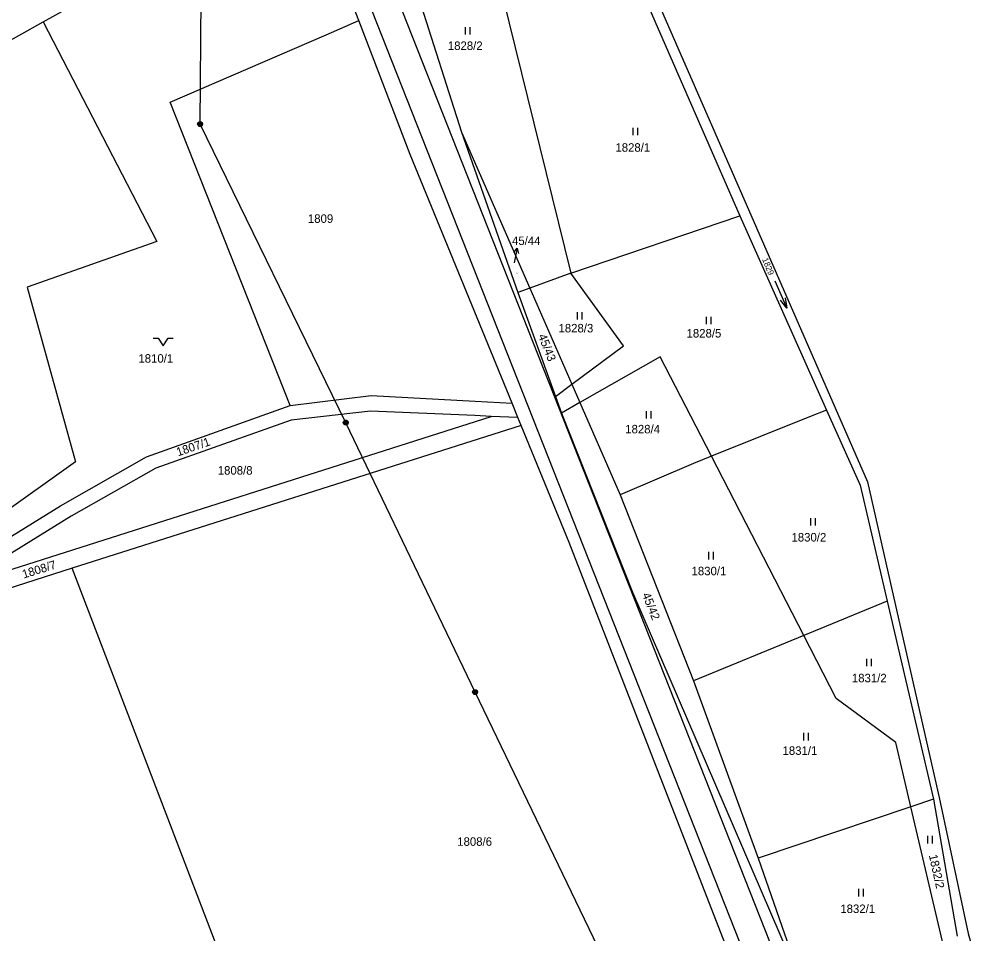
# Model space of a CAD drawing. Extents: x -609861 to -605046, y -1120287 to -1116307.
# Drawn here: x -608867.9 to -608674.5, y -1117056.1 to -1116873.3 of the extents above; entities that cross this region are included whole.
import ezdxf

# ---------------------------------------------------------------- set-up
doc = ezdxf.new("R2010")
doc.units = 0
for name, color, linetype in [('Vrstva 1', 7, 'Continuous'), ('Vrstva 2', 7, 'Continuous'), ('Vrstva 3', 7, 'Continuous'), ('Vrstva 4', 7, 'Continuous'), ('Vrstva 6', 7, 'Continuous'), ('Vrstva 7', 7, 'Continuous')]:
    doc.layers.add(name, color=color, linetype=linetype)

msp = doc.modelspace()

# ---------------------------------------------------------------- linework, layer by layer
at = {"layer": 'Vrstva 1'}
for p, q in [((-608755.13, -1116835.76), (-608704.77, -1116950.96)), ((-608756.94, -1116836.66), (-608723.86, -1116912.58)), ((-608776.76, -1116846.55), (-608757.6, -1116924.02)), ((-608799.99, -1116873.49), (-608809.1, -1116849.76)), ((-608792.64, -1116854.47), (-608779.46, -1116895.79)), ((-608863.09, -1116873.74), (-608838.32, -1116859.96)), ((-608885.48, -1116886.38), (-608863.09, -1116873.74)), ((-608863.09, -1116873.74), (-608840.34, -1116917.65)), ((-608806.56, -1116876.33), (-608799.99, -1116873.49)), ((-608789.72, -1116900.26), (-608799.99, -1116873.49)), ((-608837.71, -1116889.8), (-608806.56, -1116876.33)), ((-608813.72, -1116950.45), (-608837.71, -1116889.8)), ((-608779.46, -1116895.79), (-608768.22, -1116927.91)), ((-608779.46, -1116895.79), (-608765.81, -1116927.03)), ((-608769.36, -1116950.01), (-608789.72, -1116900.26)), ((-608757.6, -1116924.02), (-608723.86, -1116912.58)), ((-608723.86, -1116912.58), (-608706.51, -1116951.38)), ((-608840.34, -1116917.65), (-608866.31, -1116926.79)), ((-608757.6, -1116924.02), (-608765.81, -1116927.03)), ((-608747.08, -1116938.52), (-608757.6, -1116924.02)), ((-608866.31, -1116926.79), (-608856.65, -1116961.75)), ((-608765.81, -1116927.03), (-608768.22, -1116927.91)), ((-608765.81, -1116927.03), (-608757.42, -1116946.21)), ((-608768.22, -1116927.91), (-608760.7, -1116948.65)), ((-608757.42, -1116946.21), (-608747.08, -1116938.52)), ((-608739.78, -1116940.71), (-608755.81, -1116949.89)), ((-608729.53, -1116960.61), (-608739.78, -1116940.71)), ((-608760.7, -1116948.65), (-608757.42, -1116946.21)), ((-608813.72, -1116950.45), (-608797.56, -1116948.46)), ((-608797.56, -1116948.46), (-608776.73, -1116949.6)), ((-608776.73, -1116949.6), (-608769.36, -1116950.01)), ((-608768.19, -1116952.87), (-608769.36, -1116950.01)), ((-608760.7, -1116948.65), (-608759.49, -1116951.99)), ((-608755.81, -1116949.89), (-608759.49, -1116951.99)), ((-608755.81, -1116949.89), (-608747.75, -1116968.33)), ((-608842.43, -1116960.74), (-608813.72, -1116950.45)), ((-608797.65, -1116951.61), (-608813.51, -1116953.41)), ((-608776.81, -1116952.5), (-608797.65, -1116951.61)), ((-608759.49, -1116951.99), (-608745.28, -1116987.83)), ((-608706.51, -1116951.38), (-608709.94, -1116952.75)), ((-608706.51, -1116951.38), (-608699.82, -1116966.42)), ((-608704.77, -1116950.96), (-608698.32, -1116965.73)), ((-608930.49, -1117002.68), (-608773.57, -1116952.64)), ((-608813.51, -1116953.41), (-608840.59, -1116962.99)), ((-608773.57, -1116952.64), (-608776.81, -1116952.5)), ((-608768.19, -1116952.87), (-608773.57, -1116952.64)), ((-608767.54, -1116954.47), (-608768.19, -1116952.87)), ((-608709.94, -1116952.75), (-608729.53, -1116960.61)), ((-608767.54, -1116954.47), (-608857.29, -1116983.01)), ((-608757.97, -1116977.84), (-608767.54, -1116954.47)), ((-608856.65, -1116961.75), (-608887.34, -1116983.61)), ((-608859.62, -1116970.51), (-608842.43, -1116960.74)), ((-608729.53, -1116960.61), (-608733.12, -1116962.05)), ((-608711.06, -1116996.46), (-608729.53, -1116960.61)), ((-608840.59, -1116962.99), (-608857.47, -1116972.57)), ((-608733.12, -1116962.05), (-608747.75, -1116968.33)), ((-608698.32, -1116965.73), (-608693.04, -1116989.03)), ((-608699.82, -1116966.42), (-608694.41, -1116989.59)), ((-608747.75, -1116968.33), (-608733.1, -1117005.55)), ((-608878.66, -1116982.27), (-608859.62, -1116970.51)), ((-608857.47, -1116972.57), (-608876.93, -1116984.62)), ((-608717.66, -1117081.65), (-608757.97, -1116977.84)), ((-608857.29, -1116983.01), (-608906.23, -1116998.7)), ((-608787, -1117166.57), (-608857.29, -1116983.01)), ((-608745.28, -1116987.83), (-608710.81, -1117067.93)), ((-608693.04, -1116989.03), (-608684.02, -1117028.83)), ((-608694.41, -1116989.59), (-608711.06, -1116996.46)), ((-608694.41, -1116989.59), (-608685.15, -1117029.21)), ((-608711.06, -1116996.46), (-608733.1, -1117005.55)), ((-608704.58, -1117009.05), (-608711.06, -1116996.46)), ((-608733.1, -1117005.55), (-608720.16, -1117041.02)), ((-608692.7, -1117017.86), (-608704.58, -1117009.05)), ((-608689.67, -1117030.74), (-608692.7, -1117017.86)), ((-608685.15, -1117029.21), (-608689.67, -1117030.74)), ((-608685.15, -1117029.21), (-608680.39, -1117056.57)), ((-608684.02, -1117028.83), (-608678.22, -1117056.08)), ((-608689.67, -1117030.74), (-608720.16, -1117041.02)), ((-608683.35, -1117057.67), (-608689.67, -1117030.74)), ((-608720.16, -1117041.02), (-608710.81, -1117067.93)), ((-608678.22, -1117056.08), (-608674.52, -1117068.7))]:
    msp.add_line(p, q, dxfattribs=at)
at = {"layer": 'Vrstva 3'}
for p, q in [((-608778.75, -1116874.81), (-608778.75, -1116876.31)), ((-608777.75, -1116876.31), (-608777.75, -1116874.81)), ((-608745.27, -1116894.92), (-608745.27, -1116896.42)), ((-608744.27, -1116896.42), (-608744.27, -1116894.92)), ((-608716.886, -1116925.513), (-608714.474, -1116931.007)), ((-608756.35, -1116931.8), (-608756.35, -1116933.3)), ((-608755.35, -1116933.3), (-608755.35, -1116931.8)), ((-608730.61, -1116932.72), (-608730.61, -1116934.22)), ((-608729.61, -1116934.22), (-608729.61, -1116932.72)), ((-608742.56, -1116951.6), (-608742.56, -1116953.1)), ((-608741.56, -1116953.1), (-608741.56, -1116951.6)), ((-608709.7, -1116972.99), (-608709.7, -1116974.49)), ((-608708.7, -1116974.49), (-608708.7, -1116972.99)), ((-608730.09, -1116979.74), (-608730.09, -1116981.24)), ((-608729.09, -1116981.24), (-608729.09, -1116979.74)), ((-608698.55, -1117001.11), (-608698.55, -1117002.61)), ((-608697.55, -1117002.61), (-608697.55, -1117001.11)), ((-608711.1, -1117015.93), (-608711.1, -1117017.43)), ((-608710.1, -1117017.43), (-608710.1, -1117015.93)), ((-608686.34, -1117036.55), (-608686.34, -1117038.05)), ((-608685.34, -1117038.05), (-608685.34, -1117036.55)), ((-608700.15, -1117047.13), (-608700.15, -1117048.63)), ((-608699.15, -1117048.63), (-608699.15, -1117047.13))]:
    msp.add_line(p, q, dxfattribs=at)
for points in [[(-608714.82, -1116928.975), (-608714.474, -1116931.007), (-608715.736, -1116929.377)], [(-608841.08, -1116937.03), (-608840.08, -1116937.03), (-608839.08, -1116938.53), (-608838.08, -1116937.03), (-608837.08, -1116937.03)]]:
    msp.add_lwpolyline(points, dxfattribs=at)
at = {"layer": 'Vrstva 4'}
for p, q in [((-608721.43, -1117063.98), (-608834.12, -1116778.22)), ((-608812.32, -1116818.33), (-608715.82, -1117062.88)), ((-608757.42, -1116946.21), (-608755.81, -1116949.89))]:
    msp.add_line(p, q, dxfattribs=at)
at = {"layer": 'Vrstva 6'}
for p, q in [((-608831.73, -1116894.21), (-608831.36, -1116846.15)), ((-608802.61, -1116953.91), (-608831.73, -1116894.21)), ((-608776.77, -1117007.78), (-608802.61, -1116953.91)), ((-608745.96, -1117071.69), (-608776.77, -1117007.78))]:
    msp.add_line(p, q, dxfattribs=at)
for points in [[(-608831.88, -1116893.73), (-608831.57, -1116893.73), (-608831.32, -1116893.91), (-608831.22, -1116894.2), (-608831.32, -1116894.49), (-608831.57, -1116894.67), (-608831.88, -1116894.67), (-608832.13, -1116894.49), (-608832.23, -1116894.2), (-608832.13, -1116893.91), (-608831.88, -1116893.73), (-608831.85, -1116893.77), (-608831.61, -1116893.77), (-608831.45, -1116893.85), (-608832.01, -1116893.85), (-608832.09, -1116893.93), (-608831.37, -1116893.93), (-608831.37, -1116894.01), (-608832.09, -1116894.01), (-608832.13, -1116894.09), (-608831.33, -1116894.09), (-608831.29, -1116894.17), (-608832.17, -1116894.17), (-608832.17, -1116894.25), (-608831.29, -1116894.25), (-608831.32, -1116894.33), (-608832.13, -1116894.33), (-608832.12, -1116894.41), (-608831.31, -1116894.41), (-608831.36, -1116894.49), (-608832.08, -1116894.49), (-608832, -1116894.57), (-608831.44, -1116894.57), (-608831.55, -1116894.65), (-608831.89, -1116894.65)], [(-608802.76, -1116953.43), (-608802.45, -1116953.43), (-608802.2, -1116953.61), (-608802.1, -1116953.9), (-608802.2, -1116954.19), (-608802.45, -1116954.37), (-608802.76, -1116954.37), (-608803.01, -1116954.19), (-608803.11, -1116953.9), (-608803.01, -1116953.61), (-608802.76, -1116953.43), (-608802.73, -1116953.47), (-608802.49, -1116953.47), (-608802.33, -1116953.55), (-608802.89, -1116953.55), (-608802.97, -1116953.63), (-608802.25, -1116953.63), (-608802.25, -1116953.71), (-608802.97, -1116953.71), (-608803.01, -1116953.79), (-608802.21, -1116953.79), (-608802.17, -1116953.87), (-608803.05, -1116953.87), (-608803.05, -1116953.95), (-608802.17, -1116953.95), (-608802.2, -1116954.03), (-608803.01, -1116954.03), (-608803, -1116954.11), (-608802.19, -1116954.11), (-608802.24, -1116954.19), (-608802.96, -1116954.19), (-608802.88, -1116954.27), (-608802.32, -1116954.27), (-608802.43, -1116954.35), (-608802.77, -1116954.35)], [(-608776.92, -1117007.3), (-608776.61, -1117007.3), (-608776.36, -1117007.48), (-608776.26, -1117007.77), (-608776.36, -1117008.06), (-608776.61, -1117008.24), (-608776.92, -1117008.24), (-608777.17, -1117008.06), (-608777.27, -1117007.77), (-608777.17, -1117007.48), (-608776.92, -1117007.3), (-608776.89, -1117007.34), (-608776.65, -1117007.34), (-608776.49, -1117007.42), (-608777.05, -1117007.42), (-608777.13, -1117007.5), (-608776.41, -1117007.5), (-608776.41, -1117007.58), (-608777.13, -1117007.58), (-608777.17, -1117007.66), (-608776.37, -1117007.66), (-608776.33, -1117007.74), (-608777.21, -1117007.74), (-608777.21, -1117007.82), (-608776.33, -1117007.82), (-608776.36, -1117007.9), (-608777.17, -1117007.9), (-608777.16, -1117007.98), (-608776.35, -1117007.98), (-608776.4, -1117008.06), (-608777.12, -1117008.06), (-608777.04, -1117008.14), (-608776.48, -1117008.14), (-608776.59, -1117008.22), (-608776.93, -1117008.22)]]:
    msp.add_lwpolyline(points, dxfattribs=at)
at = {"layer": 'Vrstva 7'}
msp.add_line((-608768.345, -1116919.012), (-608768.95, -1116921.95), dxfattribs=at)
msp.add_lwpolyline([(-608769.036, -1116919.89), (-608768.345, -1116919.012), (-608768.057, -1116920.092)], dxfattribs=at)

# ---------------------------------------------------------------- texts
at = {"layer": 'Vrstva 2'}
for s, height, p in [('1828/2', 1.7, (-608782.207, -1116879.38)), ('1828/1', 1.7, (-608748.717, -1116899.73)), ('1809', 1.7, (-608810.177, -1116913.95)), ('45/44', 0.2, (-608768.612, -1116924.11)), ('1828/3', 1.7, (-608760.097, -1116935.86)), ('1828/5', 1.7, (-608734.497, -1116936.88)), ('1810/1', 1.7, (-608844.057, -1116941.91)), ('1828/4', 1.7, (-608746.757, -1116956.05)), ('1808/8', 1.7, (-608828.197, -1116964.3)), ('1830/2', 1.7, (-608713.527, -1116977.67)), ('1830/1', 1.7, (-608733.497, -1116984.42)), ('1831/2', 1.7, (-608701.457, -1117005.82)), ('1831/1', 1.7, (-608715.317, -1117020.33)), ('1808/6', 1.7, (-608780.327, -1117038.52)), ('1832/1', 1.7, (-608703.767, -1117051.96))]:
    msp.add_text(s, height=height, dxfattribs=at).set_placement(p)
for s, height, rotation, p in [('1829', 1.2, 292.49496, (-608719.424, -1116921.236)), ('45/43', 1.7, 291.57822, (-608764.193, -1116936.541)), ('1807/1', 1.7, 18.90761, (-608836.128, -1116960.653)), ('1808/7', 1.7, 17.07414, (-608866.985, -1116985.075)), ('45/42', 1.7, 291.57822, (-608743.413, -1116988.271)), ('1832/2', 1.7, 282.58278, (-608686.084, -1117040.423))]:
    msp.add_text(s, height=height, rotation=rotation, dxfattribs=at).set_placement(p)
at = {"layer": 'Vrstva 7'}
msp.add_text('45/44', height=1.7, dxfattribs=at).set_placement((-608769.38, -1116918.38))

doc.saveas('drawing.dxf')
